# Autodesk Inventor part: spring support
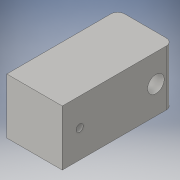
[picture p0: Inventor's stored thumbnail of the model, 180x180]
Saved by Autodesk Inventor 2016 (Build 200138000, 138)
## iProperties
Created: 2020-02
Part Number: spring support
Material: Generic
Document SubType Name: Modeling
Designer: merlin
Density: 1 g/cm^3
Appearance: Default
Author: merlin
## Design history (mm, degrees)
sketch "Sketch1"
  geometry: L1 (33.337, 20.638)-(7.937, 20.638); L2 (7.937, 20.638)-(7.937, -30.162); L3 (7.937, -30.162)-(33.337, -30.162); L4 (33.337, -30.162)-(33.337, 20.638); 1 further point
  constraints: 8 end point, 2 parallel, 1 horizontal, 1 perpendicular
  dimensions: "d0" = 25.4 distance of L3.end L2.end; "d1" = 50.8 distance of L2.end L1.end
extrude "Extrusion1" new body sketch "Sketch1" distance "d2" = 25.4; taper "d3" = 0 deg
sketch "Sketch2"
  geometry: C1 r 3.81 at (42.862, 12.7); 1 further point
  constraints: 1 centre point
  dimensions: "d4" = 7.62 diameter of C1
hole "Hole1" sketch "Sketch2" at (42.862, 12.7) diameter "d5" = 7.62; stored, may be unused: countersink angle "d9" = 82 deg, drill point angle "d11" = 118 deg; dims "d6" = 19.05, "d7" = 9.525, "d8" = 6.35, "d10" = 25.4
fillet "Fillet1" dims "d12" = 3.175
fillet "Fillet2" dims "d13" = 3.175
sketch "Sketch3"
  geometry: C1 r 1.651 at (-7.938, 12.7); 1 further point
  constraints: 1 centre point
  dimensions: "d14" = 3.302 diameter of C1
hole "Hole2" sketch "Sketch3" at (-7.938, 12.7) diameter "d15" = 3.302; stored, may be unused: countersink angle "d19" = 82 deg, drill point angle "d21" = 118 deg; dims "d16" = 19.05, "d17" = 9.525, "d18" = 6.35, "d20" = 25.4
body "Solid1"
